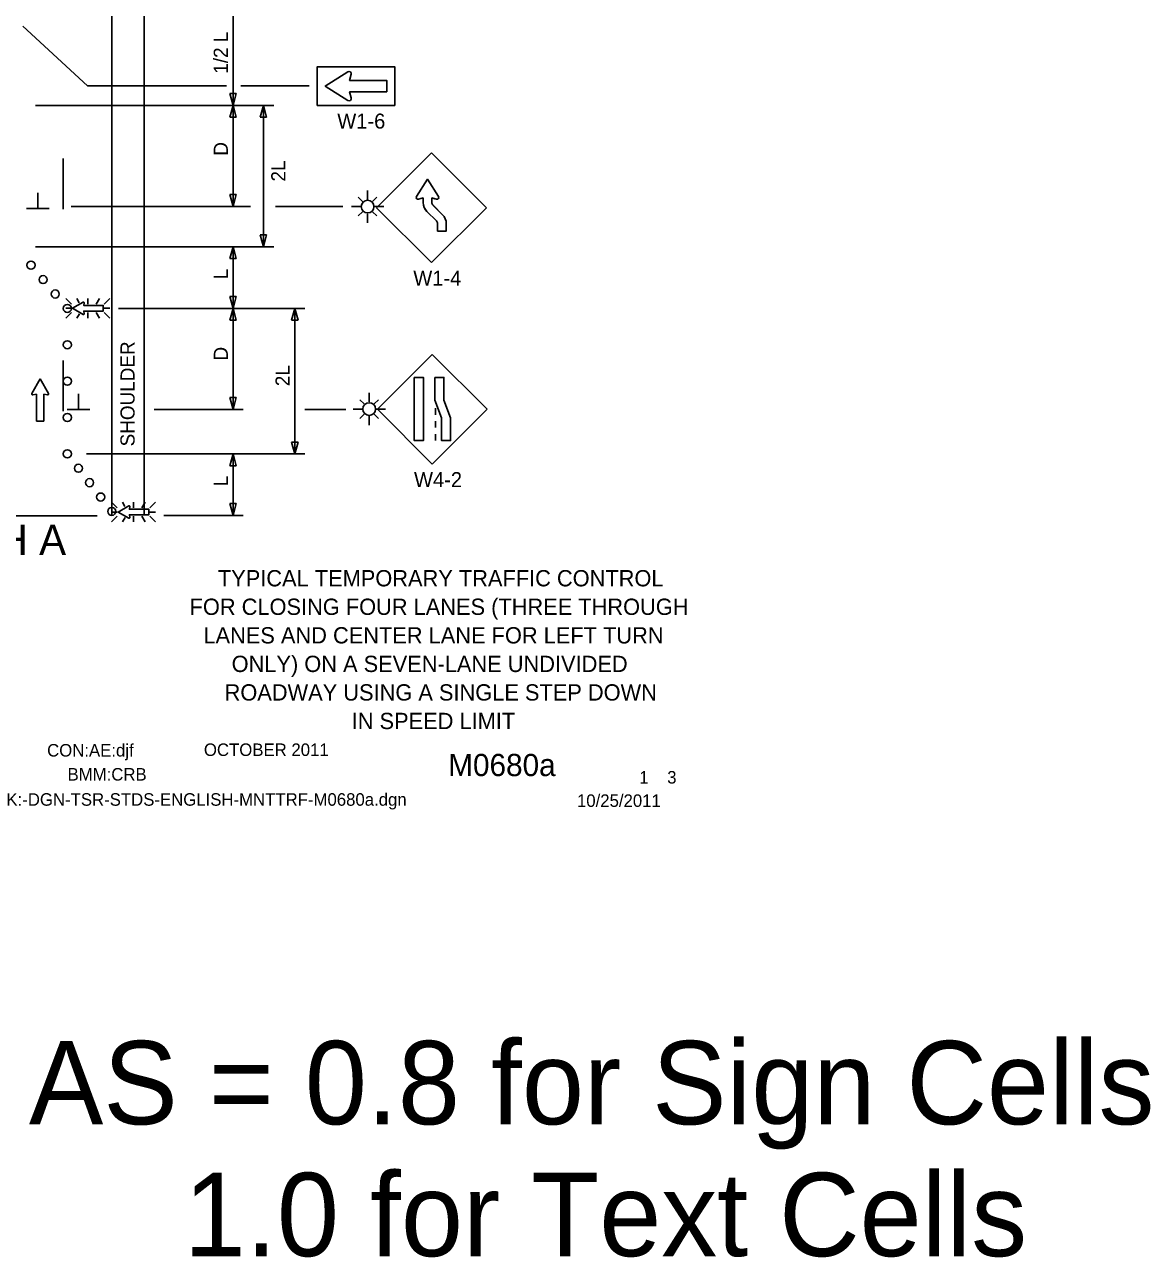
# Model space of a CAD drawing. Extents: x 16038 to 19504, y 5710 to 8321.
# Drawn here: x 17080 to 17637, y 5710 to 6320 of the extents above; entities that cross this region are included whole.
import ezdxf

# ---------------------------------------------------------------- set-up
doc = ezdxf.new("R2010")
doc.units = 0
for name, color, linetype in [('ALI_LEGAL_EX', 7, 'Continuous'), ('BORDER', 7, 'Continuous'), ('BORDER_SIGNAL_WO', 7, 'Continuous'), ('MT_SCRATCH_LEVEL_E', 7, 'Continuous'), ('PAVT_EDGE_EX', 7, 'Continuous'), ('TRAFFIC_SIGNS_PR', 7, 'Continuous'), ('TYPICAL_TEXT_DIMEN_PR', 7, 'Continuous')]:
    doc.layers.add(name, color=color, linetype=linetype)

msp = doc.modelspace()

# ---------------------------------------------------------------- linework, layer by layer
at = {"layer": 'ALI_LEGAL_EX'}
for points in [[(17098.71, 6229.12), (17098.71, 6254.12)], [(17098.71, 6129.12), (17098.71, 6154.12)]]:
    msp.add_lwpolyline(points, dxfattribs=at)
at = {"layer": 'MT_SCRATCH_LEVEL_E'}
for p, q in [((17087.24, 6145.03), (17083.12, 6137.79)), ((17087.24, 6145.03), (17083.12, 6137.79)), ((17091.38, 6137.79), (17087.24, 6145.03)), ((17091.38, 6137.79), (17087.24, 6145.03)), ((17083.61, 6137.11), (17085.38, 6137.42)), ((17083.61, 6137.11), (17085.38, 6137.42)), ((17085.38, 6137.42), (17085.38, 6124.16)), ((17085.38, 6137.42), (17085.38, 6124.16)), ((17089.13, 6124.16), (17089.13, 6137.42)), ((17089.13, 6137.42), (17090.9, 6137.11)), ((17089.13, 6124.16), (17089.13, 6137.42)), ((17089.13, 6137.42), (17090.9, 6137.11)), ((17085.38, 6124.16), (17089.13, 6124.16)), ((17085.38, 6124.16), (17089.13, 6124.16))]:
    msp.add_line(p, q, dxfattribs=at)
for centre, start, end in [((17083.53, 6137.56), 150.42484, 279.96381), ((17083.53, 6137.56), 150.42484, 279.96381), ((17090.97, 6137.57), 260.03619, 29.77312), ((17090.97, 6137.57), 260.03619, 29.77312)]:
    msp.add_arc(centre, 0.463, start, end, dxfattribs=at)
at = {"layer": 'PAVT_EDGE_EX'}
for p, q in [((17122.71, 6925.32), (17122.71, 6077.44)), ((17138.71, 6925.32), (17138.71, 6077.44))]:
    msp.add_line(p, q, dxfattribs=at)
at = {"layer": 'TRAFFIC_SIGNS_PR'}
for p, q in [((17239.51, 6297.14), (17228.35, 6290.03)), ((17240.35, 6292.84), (17241.19, 6295.9)), ((17228.35, 6290.03), (17239.51, 6282.93)), ((17258.75, 6292.84), (17240.35, 6292.84)), ((17241.19, 6284.18), (17240.35, 6287.24)), ((17240.35, 6287.24), (17258.75, 6287.24)), ((17258.75, 6292.84), (17258.75, 6287.24)), ((17253.77, 6229.82), (17280.92, 6256.98)), ((17308.07, 6229.82), (17280.92, 6256.98)), ((17249.28, 6233.91), (17249.28, 6238.42)), ((17246.77, 6232.87), (17244.66, 6234.98)), ((17251.79, 6232.87), (17253.9, 6234.98)), ((17246.13, 6230.36), (17241.29, 6230.36)), ((17246.77, 6227.85), (17244.66, 6225.74)), ((17249.28, 6222.39), (17249.28, 6226.81)), ((17251.79, 6227.85), (17253.9, 6225.74)), ((17252.43, 6230.36), (17257.32, 6230.36)), ((17280.92, 6202.67), (17253.77, 6229.82)), ((17283.34, 6223.3), (17278.62, 6228.02)), ((17283.34, 6223.3), (17278.62, 6228.02)), ((17308.07, 6229.82), (17280.92, 6202.67)), ((17281.67, 6231.07), (17286.39, 6226.36)), ((17286.39, 6226.36), (17281.68, 6231.07)), ((17099.94, 6184.87), (17102.76, 6182.05)), ((17105.38, 6184.87), (17106.59, 6182.78)), ((17110.85, 6182.05), (17110.85, 6184.87)), ((17116.64, 6184.87), (17115.01, 6182.05)), ((17118.93, 6182.05), (17121.76, 6184.88)), ((17102.76, 6180.02), (17099.94, 6180.02)), ((17099.94, 6175.17), (17102.76, 6177.99)), ((17106.67, 6177.36), (17105.4, 6175.17)), ((17110.85, 6177.99), (17110.85, 6175.17)), ((17114.98, 6177.99), (17116.61, 6175.17)), ((17118.93, 6180.02), (17121.76, 6180.02)), ((17118.93, 6177.99), (17121.76, 6175.17)), ((17281.32, 6157.21), (17254.17, 6130.05)), ((17308.48, 6130.05), (17281.32, 6157.21)), ((17247.57, 6132.65), (17245.46, 6134.76)), ((17250.08, 6133.69), (17250.08, 6138.2)), ((17252.59, 6132.65), (17254.7, 6134.76)), ((17246.93, 6130.14), (17242.09, 6130.14)), ((17253.23, 6130.14), (17258.12, 6130.14)), ((17254.17, 6130.05), (17281.32, 6102.9)), ((17281.32, 6102.9), (17308.48, 6130.05)), ((17282.97, 6130.54), (17282.97, 6127.34)), ((17247.57, 6127.63), (17245.46, 6125.52)), ((17250.08, 6122.17), (17250.08, 6126.59)), ((17252.59, 6127.63), (17254.7, 6125.52)), ((17282.97, 6124.14), (17282.97, 6120.94)), ((17282.97, 6117.74), (17282.97, 6114.54)), ((17122.54, 6083.98), (17125.36, 6081.16)), ((17127.98, 6083.98), (17129.18, 6081.89)), ((17133.44, 6081.16), (17133.44, 6083.98)), ((17139.23, 6083.98), (17137.6, 6081.16)), ((17141.53, 6081.16), (17144.35, 6083.98)), ((17125.36, 6079.13), (17122.54, 6079.13)), ((17122.54, 6074.28), (17125.36, 6077.1)), ((17129.26, 6076.46), (17128, 6074.28)), ((17133.44, 6077.1), (17133.44, 6074.28)), ((17137.58, 6077.1), (17139.21, 6074.28)), ((17141.53, 6079.13), (17144.35, 6079.13)), ((17141.53, 6077.1), (17144.35, 6074.28))]:
    msp.add_line(p, q, dxfattribs=at)
for points in [[(17262.75, 6280.44), (17224.35, 6280.44), (17224.35, 6299.64), (17262.75, 6299.64)], [(17272.43, 6145.79), (17272.43, 6114.54), (17276.92, 6114.54), (17276.92, 6145.79)], [(17282.57, 6145.79), (17282.57, 6134.61), (17285.91, 6125.73), (17285.91, 6114.54), (17290.4, 6114.54), (17290.4, 6125.73), (17287.06, 6134.61), (17287.06, 6145.79)]]:
    msp.add_lwpolyline(points, close=True, dxfattribs=at)
for points in [[(17239.51, 6282.93), (17228.35, 6290.03), (17239.51, 6297.14)], [(17241.19, 6295.9), (17240.35, 6292.84), (17258.75, 6292.84), (17258.75, 6287.24), (17240.35, 6287.24), (17241.19, 6284.18)], [(17273.47, 6235.35), (17278.95, 6243.96), (17284.43, 6235.35)], [(17273.47, 6235.35), (17278.95, 6243.96), (17284.43, 6235.35)], [(17276.8, 6232.33), (17276.79, 6234.7), (17274.43, 6234.05)], [(17276.8, 6232.33), (17276.79, 6234.7), (17274.43, 6234.05)], [(17283.47, 6234.05), (17281.11, 6234.7), (17281.11, 6232.4)], [(17283.47, 6234.05), (17282.64, 6234.28), (17281.11, 6234.7), (17281.11, 6232.4)], [(17288.26, 6221.94), (17288.26, 6218.24), (17283.94, 6218.24), (17283.94, 6221.94)], [(17108.52, 6177.01), (17103.21, 6180.02), (17108.52, 6183.06)], [(17109.02, 6182.7), (17108.79, 6181.41), (17118.51, 6181.41), (17118.51, 6178.66), (17108.79, 6178.66), (17109.02, 6177.36)], [(17131.12, 6076.11), (17125.81, 6079.13), (17131.12, 6082.17)], [(17131.62, 6081.81), (17131.39, 6080.51), (17141.11, 6080.51), (17141.11, 6077.77), (17131.39, 6077.77), (17131.62, 6076.47)]]:
    msp.add_lwpolyline(points, dxfattribs=at)
for centre, radius in [((17249.28, 6230.36), 3.15), ((17082.71, 6201.37), 2), ((17088.71, 6194.23), 2), ((17094.71, 6187.09), 2), ((17100.71, 6179.95), 2), ((17100.71, 6161.95), 2), ((17100.71, 6143.95), 2), ((17250.08, 6130.14), 3.15), ((17100.71, 6125.95), 2), ((17100.71, 6107.95), 2), ((17106.21, 6100.82), 2), ((17111.7, 6093.69), 2), ((17117.2, 6086.56), 2), ((17122.7, 6079.44), 2)]:
    msp.add_circle(centre, radius, dxfattribs=at)
for centre, radius, start, end in [((17240.11, 6296.19), 1.12, 344.67308, 122.46963), ((17240.11, 6296.19), 1.12, 344.67308, 122.46962), ((17240.11, 6283.88), 1.12, 237.53038, 15.32692), ((17240.11, 6283.88), 1.12, 237.53038, 15.32692), ((17274.2, 6234.88), 0.866, 147.7292, 285.31719), ((17274.2, 6234.88), 0.866, 147.71964, 285.32011), ((17264.36, 6241.14), 10.8, 327.53351, 327.54311), ((17277.28, 6223.63), 10.8, 105.31922, 105.32004), ((17282.97, 6232.4), 6.17, 180.61811, 225.78746), ((17282.97, 6232.4), 6.17, 180.62445, 225.23128), ((17282.97, 6232.4), 1.85, 179.8762, 225.7877), ((17282.97, 6232.4), 1.85, 180, 225.78746), ((17283.7, 6234.88), 0.866, 254.61481, 32.47119), ((17282.09, 6221.94), 6.17, 0, 45.78828), ((17282.09, 6221.94), 1.85, 0, 47.62801), ((17108.69, 6182.76), 0.341, 350.04067, 118.51671), ((17108.69, 6177.31), 0.341, 241.10835, 9.26922), ((17131.28, 6081.87), 0.341, 350.04067, 118.51671), ((17131.28, 6076.41), 0.341, 241.10835, 9.26922)]:
    msp.add_arc(centre, radius, start, end, dxfattribs=at)
at = {"layer": 'TYPICAL_TEXT_DIMEN_PR'}
for p, q in [((17182.71, 6280.46), (17182.71, 6342.13)), ((17078.72, 6319.64), (17110.7, 6290.12)), ((17179.54, 6290.12), (17110.7, 6290.12)), ((17220.43, 6290.12), (17186.53, 6290.12)), ((17182.71, 6280.46), (17181.14, 6286.33)), ((17181.14, 6286.33), (17182.71, 6286.33)), ((17182.71, 6286.33), (17184.28, 6286.33)), ((17184.28, 6286.33), (17182.71, 6280.46)), ((17202.83, 6280.46), (17084.95, 6280.46)), ((17182.71, 6280.46), (17181.14, 6274.6)), ((17182.71, 6230.46), (17182.71, 6280.46)), ((17184.28, 6274.6), (17182.71, 6280.46)), ((17196.14, 6274.6), (17197.71, 6280.46)), ((17197.71, 6210.46), (17197.71, 6280.46)), ((17197.71, 6280.46), (17199.28, 6274.6)), ((17181.14, 6274.6), (17182.71, 6274.6)), ((17182.71, 6274.6), (17184.28, 6274.6)), ((17197.71, 6274.6), (17196.14, 6274.6)), ((17199.28, 6274.6), (17197.71, 6274.6)), ((17086.07, 6229.41), (17086.07, 6237.19)), ((17182.71, 6230.46), (17181.14, 6236.33)), ((17181.14, 6236.33), (17182.71, 6236.33)), ((17182.71, 6236.33), (17184.28, 6236.33)), ((17184.28, 6236.33), (17182.71, 6230.46)), ((17091.7, 6229.41), (17080.45, 6229.41)), ((17191.28, 6230.46), (17102.58, 6230.46)), ((17237.05, 6230.46), (17203.66, 6230.46)), ((17197.71, 6210.46), (17196.14, 6216.32)), ((17196.14, 6216.32), (17197.71, 6216.32)), ((17197.71, 6216.32), (17199.28, 6216.32)), ((17199.28, 6216.32), (17197.71, 6210.46)), ((17202.83, 6210.46), (17084.95, 6210.46)), ((17182.71, 6210.46), (17181.14, 6204.6)), ((17182.71, 6179.95), (17182.71, 6210.46)), ((17184.28, 6204.6), (17182.71, 6210.46)), ((17181.14, 6204.6), (17182.71, 6204.6)), ((17182.71, 6204.6), (17184.28, 6204.6)), ((17182.71, 6179.95), (17181.14, 6185.81)), ((17181.14, 6185.81), (17182.71, 6185.81)), ((17182.71, 6185.81), (17184.28, 6185.81)), ((17184.28, 6185.81), (17182.71, 6179.95)), ((17187.71, 6179.95), (17126.02, 6179.95)), ((17218.29, 6179.95), (17128.01, 6179.95)), ((17181.14, 6174.09), (17182.71, 6179.95)), ((17182.71, 6179.95), (17184.28, 6174.09)), ((17182.71, 6179.95), (17182.71, 6129.95)), ((17213.29, 6179.95), (17211.72, 6174.09)), ((17213.29, 6107.95), (17213.29, 6179.95)), ((17214.86, 6174.09), (17213.29, 6179.95)), ((17182.71, 6174.09), (17181.14, 6174.09)), ((17184.28, 6174.09), (17182.71, 6174.09)), ((17211.72, 6174.09), (17213.29, 6174.09)), ((17213.29, 6174.09), (17214.86, 6174.09)), ((17106.22, 6129.95), (17106.22, 6137.74)), ((17182.71, 6129.95), (17181.14, 6135.81)), ((17181.14, 6135.81), (17182.71, 6135.81)), ((17182.71, 6135.81), (17184.28, 6135.81)), ((17184.28, 6135.81), (17182.71, 6129.95)), ((17111.84, 6129.95), (17100.59, 6129.95)), ((17187.71, 6129.95), (17143.72, 6129.95)), ((17161.71, 6129.95), (17187.71, 6129.95)), ((17238.51, 6129.95), (17218.29, 6129.95)), ((17213.29, 6107.95), (17211.72, 6113.81)), ((17211.72, 6113.81), (17213.29, 6113.81)), ((17213.29, 6113.81), (17214.86, 6113.81)), ((17214.86, 6113.81), (17213.29, 6107.95)), ((17218.29, 6107.95), (17110.17, 6107.95)), ((17182.71, 6107.95), (17181.14, 6102.09)), ((17182.71, 6077.44), (17182.71, 6107.95)), ((17184.28, 6102.09), (17182.71, 6107.95)), ((17181.14, 6102.09), (17182.71, 6102.09)), ((17182.71, 6102.09), (17184.28, 6102.09)), ((17182.71, 6077.44), (17181.14, 6083.3)), ((17181.14, 6083.3), (17182.71, 6083.3)), ((17182.71, 6083.3), (17184.28, 6083.3)), ((17184.28, 6083.3), (17182.71, 6077.44)), ((16936.37, 6077.28), (17115.53, 6077.28)), ((17187.71, 6077.44), (17148.38, 6077.44))]:
    msp.add_line(p, q, dxfattribs=at)

# ---------------------------------------------------------------- texts
at = {"layer": 'BORDER'}
for s, p in [('TYPICAL TEMPORARY TRAFFIC CONTROL', (17175.21, 6042.33)), ('FOR CLOSING FOUR LANES (THREE THROUGH', (17161.21, 6028.2)), ('LANES AND CENTER LANE FOR LEFT TURN', (17168.04, 6014.06)), ('ONLY) ON A SEVEN-LANE UNDIVIDED', (17182.02, 5999.92)), ('ROADWAY USING A SINGLE STEP DOWN', (17178.54, 5985.79)), ('IN SPEED LIMIT', (17241.42, 5971.65))]:
    msp.add_text(s, height=8.066, dxfattribs=at).set_placement(p)
at = {"layer": 'BORDER_SIGNAL_WO'}
for s, height, p in [('CON:AE:djf', 6.2, (17090.69, 5958.06)), ('    OCTOBER 2011    ', 6.2, (17159.08, 5958.34)), ('    M0680a   ', 11, (17272.86, 5948.38)), ('BMM:CRB   ', 6.2, (17100.81, 5946.17)), (' 1    3 ', 6.2, (17381.45, 5944.7)), ('K:-DGN-TSR-STDS-ENGLISH-MNTTRF-M0680a.dgn        ', 6.2, (17070.55, 5933.71)), ('10/25/2011    ', 6.2, (17352.93, 5933.13)), ('AS = 0.8 for Sign Cells', 41.2877, (17081.69, 5775.96)), ('     1.0 for Text Cells', 41.2877, (17081.69, 5710.67))]:
    msp.add_text(s, height=height, dxfattribs=at).set_placement(p)
at = {"layer": 'TRAFFIC_SIGNS_PR'}
for s, p in [('W1-6', (17234.29, 6268.99)), ('W1-4', (17271.92, 6191.23)), ('W4-2', (17272.28, 6091.46))]:
    msp.add_text(s, height=7.44, dxfattribs=at).set_placement(p)
at = {"layer": 'TYPICAL_TEXT_DIMEN_PR'}
for s, p in [('1/2 L', (17180.15, 6296.18)), ('D', (17180.15, 6255.57)), ('2L', (17208.62, 6242.78)), ('L', (17180.15, 6194.35)), ('SHOULDER', (17133.99, 6111.64)), ('D', (17180.15, 6154.17)), ('2L', (17210.73, 6141.44)), ('L', (17180.15, 6091.84))]:
    msp.add_text(s, height=7, rotation=90, dxfattribs=at).set_placement(p)
msp.add_text('A MATCH A', height=15, dxfattribs=at).set_placement((16990.88, 6057.87))

doc.saveas('drawing.dxf')
